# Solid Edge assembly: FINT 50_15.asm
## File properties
Title: Zylinder
Author: bmolnar
Template: iso assembly.asm
Last saved by: bmolnar
Revision: 7
Application: Solid Edge
Username: bmolnar
Dokumentum tartalom típus: 1
Document Number: FINT 50/15
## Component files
hrungsstange.par
Profilrohr.par
Platte.par
Kolbenstange.par
Kit_1.par
Kit_2.par
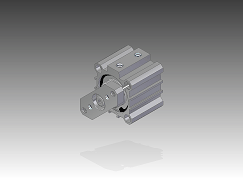
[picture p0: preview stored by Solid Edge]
